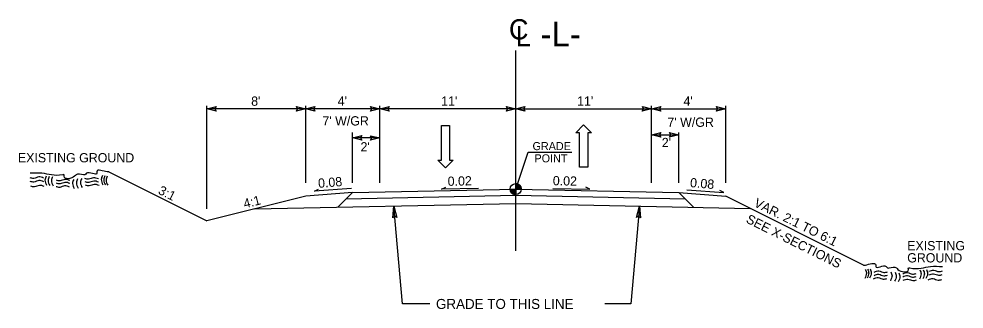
# Model space of a CAD drawing. Extents: x 575722 to 576066, y -53107 to -52774.
# Drawn here: x 575984.6 to 576061.2, y -53095.3 to -53071.8 of the extents above; entities that cross this region are included whole.
import ezdxf

# ---------------------------------------------------------------- set-up
doc = ezdxf.new("R2010")
doc.units = 0
for name, color, linetype in [('Old_Level_2', 7, 'Continuous'), ('Prop Dimension Text', 7, 'Continuous'), ('Prop Lane Arrow CELL', 7, 'Continuous'), ('Typical Grade Point Symbol CELL', 7, 'Continuous'), ('Typical Pavement Slope CELL', 7, 'Continuous'), ('Typical Slope Point Local CELL', 7, 'Continuous'), ('Typical Terminator CELL', 7, 'Continuous'), ('Typical Text Centerline CELL', 7, 'Continuous'), ('Typical Text Grade Point CELL', 7, 'Continuous')]:
    doc.layers.add(name, color=color, linetype=linetype)

# ---------------------------------------------------------------- blocks, each defined once
blk = doc.blocks.new('TERMINATOR')
at = {"layer": 'Typical Terminator CELL'}
blk.add_lwpolyline([(-0.469, 0.081), (0, 0), (-0.471, -0.083), (-0.411, 0)], close=True, dxfattribs=at)

msp = doc.modelspace()

# ---------------------------------------------------------------- linework, layer by layer
at = {"layer": 'Old_Level_2'}
for points in [[(575991.923, -53084.176), (575991.78, -53084.161), (575990.94, -53084.161), (575990.94, -53084.281), (575990.1, -53084.281), (575989.98, -53084.401), (575989.86, -53084.401), (575989.26, -53084.401), (575989.14, -53084.521), (575988.3, -53084.521), (575988.3, -53084.401), (575988.18, -53084.401), (575986.5, -53084.281), (575985.543, -53084.281)], [(575986.632, -53084.669), (575986.242, -53084.575), (575985.839, -53084.696), (575985.543, -53084.642)], [(575986.84, -53084.514), (575986.746, -53084.837), (575986.881, -53085.254)], [(575987.096, -53084.541), (575987.002, -53084.864), (575987.136, -53085.28)], [(575987.365, -53084.555), (575987.271, -53084.877), (575987.405, -53085.294)], [(575989.717, -53084.702), (575989.623, -53085.025), (575989.757, -53085.442)], [(575991.067, -53084.736), (575990.678, -53084.642), (575990.274, -53084.763), (575989.979, -53084.709)], [(575991.397, -53084.474), (575991.303, -53084.796), (575991.437, -53085.213)], [(575991.598, -53084.487), (575991.504, -53084.81), (575991.639, -53085.227)], [(575991.787, -53084.514), (575991.692, -53084.837), (575991.827, -53085.254)], [(575986.645, -53084.965), (575986.256, -53084.871), (575985.852, -53084.991), (575985.557, -53084.938)], [(575986.686, -53085.354), (575986.296, -53085.26), (575985.893, -53085.381), (575985.597, -53085.327)], [(575988.729, -53085.395), (575988.339, -53085.301), (575987.936, -53085.422), (575987.64, -53085.368)], [(575988.756, -53084.871), (575988.366, -53084.776), (575987.963, -53084.897), (575987.667, -53084.844)], [(575988.756, -53085.112), (575988.366, -53085.018), (575987.963, -53085.139), (575987.667, -53085.086)], [(575989.072, -53084.783), (575988.977, -53085.106), (575989.112, -53085.522)], [(575989.381, -53084.743), (575989.287, -53085.065), (575989.421, -53085.482)], [(575991.081, -53085.005), (575990.691, -53084.911), (575990.288, -53085.032), (575989.992, -53084.978)], [(575991.121, -53085.274), (575990.731, -53085.18), (575990.328, -53085.301), (575990.032, -53085.247)], [(576053.018, -53091.723), (576053.161, -53091.707), (576054.001, -53091.707), (576054.001, -53091.827), (576054.841, -53091.827), (576054.961, -53091.947), (576055.081, -53091.947), (576055.681, -53091.947), (576055.801, -53092.067), (576056.641, -53092.067), (576056.641, -53091.947), (576056.761, -53091.947), (576058.441, -53091.827), (576059.397, -53091.827)], [(576053.154, -53092.06), (576053.248, -53092.383), (576053.114, -53092.8)], [(576053.342, -53092.034), (576053.436, -53092.356), (576053.302, -53092.773)], [(576053.544, -53092.02), (576053.638, -53092.343), (576053.503, -53092.759)], [(576053.873, -53092.282), (576054.263, -53092.188), (576054.666, -53092.309), (576054.962, -53092.255)], [(576055.224, -53092.249), (576055.318, -53092.571), (576055.184, -53092.988)], [(576055.56, -53092.289), (576055.654, -53092.611), (576055.52, -53093.028)], [(576055.869, -53092.329), (576055.963, -53092.652), (576055.829, -53093.069)], [(576056.185, -53092.417), (576056.575, -53092.323), (576056.978, -53092.444), (576057.274, -53092.39)], [(576057.576, -53092.101), (576057.67, -53092.423), (576057.536, -53092.84)], [(576057.845, -53092.087), (576057.939, -53092.41), (576057.804, -53092.827)], [(576058.1, -53092.06), (576058.194, -53092.383), (576058.06, -53092.8)], [(576058.309, -53092.215), (576058.698, -53092.121), (576059.102, -53092.242), (576059.397, -53092.188)], [(576053.819, -53092.82), (576054.209, -53092.726), (576054.612, -53092.847), (576054.908, -53092.793)], [(576053.86, -53092.551), (576054.25, -53092.457), (576054.653, -53092.578), (576054.948, -53092.524)], [(576056.185, -53092.659), (576056.575, -53092.565), (576056.978, -53092.685), (576057.274, -53092.632)], [(576056.212, -53092.941), (576056.602, -53092.847), (576057.005, -53092.968), (576057.301, -53092.914)], [(576058.255, -53092.901), (576058.645, -53092.806), (576059.048, -53092.927), (576059.344, -53092.874)], [(576058.295, -53092.511), (576058.685, -53092.417), (576059.088, -53092.538), (576059.384, -53092.484)]]:
    msp.add_spline(points, degree=3, dxfattribs=at)
at = {"layer": 'Prop Dimension Text'}
for p, q in [((575999.853, -53087.165), (575999.853, -53078.813)), ((576007.853, -53079.063), (575999.853, -53079.063)), ((576007.853, -53084.563), (576007.853, -53078.813)), ((576007.853, -53085.043), (576007.853, -53078.813)), ((576013.853, -53079.063), (576007.853, -53079.063)), ((576013.853, -53084.563), (576013.853, -53078.813)), ((576013.853, -53085.043), (576013.853, -53078.813)), ((576013.853, -53084.563), (576013.853, -53078.813)), ((576024.853, -53079.063), (576013.853, -53079.063)), ((576024.853, -53079.063), (576035.853, -53079.063)), ((576035.853, -53083.704), (576035.853, -53078.813)), ((576035.853, -53085.043), (576035.853, -53078.813)), ((576035.853, -53084.563), (576035.853, -53078.813)), ((576035.853, -53079.063), (576041.853, -53079.063)), ((576041.853, -53085.043), (576041.853, -53078.813)), ((576041.853, -53084.563), (576041.853, -53078.813)), ((576011.644, -53085.043), (576011.644, -53080.97)), ((576013.853, -53081.423), (576011.644, -53081.423)), ((576035.853, -53081.176), (576038.062, -53081.176)), ((576038.062, -53085.043), (576038.062, -53080.97)), ((576015.68, -53094.86), (576014.987, -53086.935)), ((576034.872, -53086.938), (576034.179, -53094.863)), ((576017.892, -53094.86), (576015.68, -53094.86)), ((576034.179, -53094.86), (576032.075, -53094.86))]:
    msp.add_line(p, q, dxfattribs=at)
at = {"layer": 'Prop Lane Arrow CELL'}
for p, q in [((576018.836, -53083.215), (576018.836, -53080.415)), ((576018.836, -53080.415), (576019.496, -53080.415)), ((576019.496, -53080.415), (576019.496, -53083.215)), ((576029.73, -53080.996), (576030.35, -53080.366)), ((576030.35, -53080.366), (576030.99, -53080.996)), ((576030.03, -53080.996), (576029.73, -53080.996)), ((576030.03, -53083.796), (576030.03, -53080.996)), ((576030.99, -53080.996), (576030.69, -53080.996)), ((576030.69, -53080.996), (576030.69, -53083.796)), ((576019.176, -53083.845), (576018.536, -53083.215)), ((576018.536, -53083.215), (576018.836, -53083.215)), ((576019.796, -53083.215), (576019.176, -53083.845)), ((576019.496, -53083.215), (576019.796, -53083.215)), ((576030.69, -53083.796), (576030.03, -53083.796))]:
    msp.add_line(p, q, dxfattribs=at)
at = {"layer": 'Typical Grade Point Symbol CELL'}
for p, q in [((576024.853, -53085.563), (576025.853, -53082.563)), ((576024.853, -53085.563), (576024.853, -53085.115)), ((576024.405, -53085.563), (576024.853, -53085.563)), ((576024.852, -53086.011), (576024.853, -53085.563)), ((576024.853, -53085.563), (576024.852, -53086.011)), ((576025.301, -53085.563), (576024.853, -53085.563))]:
    msp.add_line(p, q, dxfattribs=at)
for points in [[(576024.857, -53085.115), (576024.857, -53085.115), (576024.857, -53085.563)], [(576024.866, -53085.115), (576024.866, -53085.563)], [(576024.875, -53085.116), (576024.875, -53085.563)], [(576024.884, -53085.116), (576024.884, -53085.563)], [(576024.893, -53085.117), (576024.893, -53085.563)], [(576024.902, -53085.118), (576024.902, -53085.563)], [(576024.911, -53085.119), (576024.911, -53085.563)], [(576024.92, -53085.12), (576024.92, -53085.563)], [(576024.929, -53085.121), (576024.929, -53085.563)], [(576024.938, -53085.123), (576024.938, -53085.563)], [(576024.947, -53085.125), (576024.947, -53085.563)], [(576024.956, -53085.127), (576024.956, -53085.563)], [(576024.964, -53085.129), (576024.964, -53085.563)], [(576024.973, -53085.132), (576024.973, -53085.563)], [(576024.982, -53085.134), (576024.982, -53085.563)], [(576024.991, -53085.137), (576024.991, -53085.563)], [(576025, -53085.14), (576025, -53085.563)], [(576025.009, -53085.143), (576025.009, -53085.563)], [(576025.018, -53085.147), (576025.018, -53085.563)], [(576025.027, -53085.151), (576025.027, -53085.563)], [(576025.036, -53085.155), (576025.036, -53085.563)], [(576025.045, -53085.159), (576025.045, -53085.563)], [(576025.054, -53085.163), (576025.054, -53085.563)], [(576025.063, -53085.168), (576025.063, -53085.563)], [(576025.072, -53085.173), (576025.072, -53085.563)], [(576025.081, -53085.178), (576025.081, -53085.563)], [(576025.09, -53085.183), (576025.09, -53085.563)], [(576025.099, -53085.189), (576025.099, -53085.563)], [(576025.108, -53085.195), (576025.108, -53085.563)], [(576025.117, -53085.202), (576025.117, -53085.563)], [(576025.126, -53085.208), (576025.126, -53085.563)], [(576025.135, -53085.215), (576025.135, -53085.563)], [(576025.143, -53085.223), (576025.143, -53085.563)], [(576025.152, -53085.231), (576025.152, -53085.563)], [(576025.161, -53085.239), (576025.161, -53085.563)], [(576025.17, -53085.248), (576025.17, -53085.563)], [(576025.179, -53085.257), (576025.179, -53085.563)], [(576025.188, -53085.267), (576025.188, -53085.563)], [(576025.197, -53085.278), (576025.197, -53085.563)], [(576025.206, -53085.288), (576025.206, -53085.563)], [(576025.215, -53085.3), (576025.215, -53085.563)], [(576025.224, -53085.313), (576025.224, -53085.563)], [(576025.233, -53085.327), (576025.233, -53085.563)], [(576025.242, -53085.342), (576025.242, -53085.563)], [(576025.251, -53085.358), (576025.251, -53085.563)], [(576025.26, -53085.377), (576025.26, -53085.563)], [(576025.269, -53085.398), (576025.269, -53085.563)], [(576025.278, -53085.423), (576025.278, -53085.563)], [(576025.287, -53085.454), (576025.287, -53085.563)], [(576025.296, -53085.499), (576025.296, -53085.563)], [(576024.407, -53085.563), (576024.407, -53085.612)], [(576024.416, -53085.563), (576024.416, -53085.664)], [(576024.425, -53085.563), (576024.425, -53085.696)], [(576024.434, -53085.563), (576024.434, -53085.723)], [(576024.443, -53085.563), (576024.443, -53085.744)], [(576024.452, -53085.563), (576024.452, -53085.763)], [(576024.461, -53085.563), (576024.461, -53085.78)], [(576024.47, -53085.563), (576024.47, -53085.796)], [(576024.479, -53085.563), (576024.479, -53085.81)], [(576024.488, -53085.563), (576024.488, -53085.823)], [(576024.497, -53085.563), (576024.497, -53085.835)], [(576024.506, -53085.563), (576024.506, -53085.845)], [(576024.515, -53085.563), (576024.515, -53085.856)], [(576024.524, -53085.563), (576024.524, -53085.866)], [(576024.533, -53085.563), (576024.533, -53085.876)], [(576024.542, -53085.563), (576024.542, -53085.885)], [(576024.551, -53085.563), (576024.551, -53085.893)], [(576024.56, -53085.563), (576024.56, -53085.901)], [(576024.569, -53085.563), (576024.569, -53085.909)], [(576024.578, -53085.563), (576024.578, -53085.916)], [(576024.587, -53085.563), (576024.587, -53085.923)], [(576024.595, -53085.563), (576024.595, -53085.929)], [(576024.604, -53085.563), (576024.604, -53085.935)], [(576024.613, -53085.563), (576024.613, -53085.941)], [(576024.622, -53085.563), (576024.622, -53085.947)], [(576024.631, -53085.563), (576024.631, -53085.952)], [(576024.64, -53085.563), (576024.64, -53085.957)], [(576024.649, -53085.563), (576024.649, -53085.962)], [(576024.658, -53085.563), (576024.658, -53085.966)], [(576024.667, -53085.563), (576024.667, -53085.97)], [(576024.676, -53085.563), (576024.676, -53085.974)], [(576024.685, -53085.563), (576024.685, -53085.978)], [(576024.694, -53085.563), (576024.694, -53085.982)], [(576024.703, -53085.563), (576024.703, -53085.985)], [(576024.712, -53085.563), (576024.712, -53085.988)], [(576024.721, -53085.563), (576024.721, -53085.991)], [(576024.73, -53085.563), (576024.73, -53085.993)], [(576024.739, -53085.563), (576024.739, -53085.996)], [(576024.748, -53085.563), (576024.748, -53085.998)], [(576024.757, -53085.563), (576024.757, -53086)], [(576024.766, -53085.563), (576024.766, -53086.002)], [(576024.774, -53085.563), (576024.774, -53086.004)], [(576024.783, -53085.563), (576024.783, -53086.005)], [(576024.792, -53085.563), (576024.792, -53086.007)], [(576024.801, -53085.563), (576024.801, -53086.008)], [(576024.81, -53085.563), (576024.81, -53086.009)], [(576024.819, -53085.563), (576024.819, -53086.01)], [(576024.828, -53085.563), (576024.828, -53086.01)], [(576024.837, -53085.563), (576024.837, -53086.011)], [(576024.846, -53085.563), (576024.846, -53086.011), (576024.846, -53086.011)]]:
    msp.add_lwpolyline(points, dxfattribs=at)
msp.add_circle((576024.853, -53085.563), 0.448, dxfattribs=at)
for start, end in [(359.99048, 89.99048), (179.99048, 269.99048)]:
    msp.add_arc((576024.853, -53085.563), 0.448, start, end, dxfattribs=at)
at = {"layer": 'Typical Pavement Slope CELL'}
for p, q in [((576018.853, -53085.563), (576019.186, -53085.396)), ((576030.853, -53085.563), (576030.52, -53085.396)), ((576011.644, -53085.838), (576007.85, -53086.141)), ((576011.551, -53085.502), (576008.551, -53085.742)), ((576008.551, -53085.742), (576008.885, -53085.575)), ((576011.644, -53085.838), (576010.452, -53087.029)), ((576021.853, -53085.5), (576018.853, -53085.563)), ((576027.853, -53085.5), (576030.853, -53085.563)), ((576038.062, -53085.838), (576041.856, -53086.141)), ((576039.254, -53087.029), (576038.062, -53085.838)), ((576038.701, -53085.609), (576041.701, -53085.849)), ((576041.701, -53085.849), (576041.368, -53085.683))]:
    msp.add_line(p, q, dxfattribs=at)
for points in [[(576011.133, -53086.348), (576024.853, -53086.063), (576038.573, -53086.348)], [(576011.644, -53085.838), (576024.853, -53085.563), (576038.062, -53085.838)], [(576003.739, -53087.169), (576024.853, -53086.73), (576043.822, -53087.124)]]:
    msp.add_lwpolyline(points, dxfattribs=at)
at = {"layer": 'Typical Slope Point Local CELL'}
for p, q in [((575991.923, -53084.176), (575999.852, -53088.141)), ((576007.85, -53086.141), (575999.852, -53088.141)), ((576053.018, -53091.723), (576041.856, -53086.141))]:
    msp.add_line(p, q, dxfattribs=at)
at = {"layer": 'Typical Terminator CELL'}
for points in [[(576014.907, -53087.883), (576014.987, -53086.935), (576015.235, -53087.859), (576015.058, -53087.755)], [(576034.63, -53087.858), (576034.872, -53086.938), (576034.956, -53087.892), (576034.8, -53087.758)]]:
    msp.add_lwpolyline(points, close=True, dxfattribs=at)
at = {"layer": 'Typical Text Centerline CELL'}
msp.add_line((576024.853, -53090.563), (576024.853, -53074.341), dxfattribs=at)
at = {"layer": 'Typical Text Grade Point CELL'}
msp.add_line((576025.853, -53082.563), (576029.391, -53082.563), dxfattribs=at)

# ---------------------------------------------------------------- block references
at = {"layer": 'Prop Dimension Text', "xscale": 1.5906680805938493, "yscale": 2.2831050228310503, "rotation": 180}
for p in [(575999.853, -53079.063), (576007.853, -53079.063), (576013.853, -53079.063), (576024.853, -53079.063), (576035.853, -53079.063), (576011.644, -53081.423), (576035.853, -53081.176)]:
    msp.add_blockref('TERMINATOR', p, dxfattribs=at)
at = {"layer": 'Prop Dimension Text', "xscale": 1.5906680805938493, "yscale": 2.2831050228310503}
for p in [(576007.853, -53079.063), (576013.853, -53079.063), (576024.853, -53079.063), (576035.853, -53079.063), (576041.853, -53079.063), (576013.853, -53081.423), (576038.062, -53081.176)]:
    msp.add_blockref('TERMINATOR', p, dxfattribs=at)

# ---------------------------------------------------------------- texts
at = {"layer": 'Prop Dimension Text'}
for s, height, p in [('-L-', 2, (576026.857, -53074.01)), ("8'", 0.75, (576003.438, -53078.813)), ("4'", 0.75, (576010.438, -53078.813)), ("11'", 0.75, (576018.821, -53078.813)), ("11'", 0.75, (576029.821, -53078.813)), ("4'", 0.75, (576038.438, -53078.813)), ("7' W/GR", 0.75, (576009.208, -53080.412)), ("7' W/GR", 0.75, (576037.135, -53080.521)), ("2'", 0.75, (576036.682, -53082.166)), ("2'", 0.75, (576012.291, -53082.516)), ('GRADE TO THIS LINE', 0.81, (576018.4, -53095.265))]:
    msp.add_text(s, height=height, dxfattribs=at).set_placement(p)
for s, rotation, p in [('0.08', 4.57392, (576008.885, -53085.467)), ('0.02', 1.19158, (576019.353, -53085.302)), ('0.02', 358.80842, (576027.853, -53085.25)), ('0.08', 355.42608, (576038.947, -53085.4))]:
    msp.add_text(s, height=0.75, rotation=rotation, dxfattribs=at).set_placement(p)
at = {"layer": 'Typical Slope Point Local CELL'}
for s, rotation, p in [('3:1', 333.43495, (575995.847, -53085.911)), ('4:1', 14.03624, (576002.915, -53087.123)), ('VAR. 2:1 TO 6:1', 333.43404, (576044.079, -53086.928)), ('SEE X-SECTIONS', 333.43404, (576043.442, -53088.239))]:
    msp.add_text(s, height=0.75, rotation=rotation, dxfattribs=at).set_placement(p)
at = {"layer": 'Typical Text Centerline CELL'}
msp.add_text('C', height=1.64, dxfattribs=at).set_placement((576024.307, -53073.447))
msp.add_text('L', height=1.641, rotation=359.9469, dxfattribs=at).set_placement((576024.852, -53074.007))
at = {"layer": 'Typical Text Grade Point CELL'}
for s, height, p in [('GRADE', 0.6525, (576026.217, -53082.407)), ('EXISTING GROUND', 0.75, (575984.552, -53083.397)), ('POINT', 0.6525, (576026.374, -53083.396)), ('EXISTING', 0.75, (576056.547, -53090.517)), ('GROUND', 0.75, (576056.547, -53091.5))]:
    msp.add_text(s, height=height, dxfattribs=at).set_placement(p)

doc.saveas('drawing.dxf')
